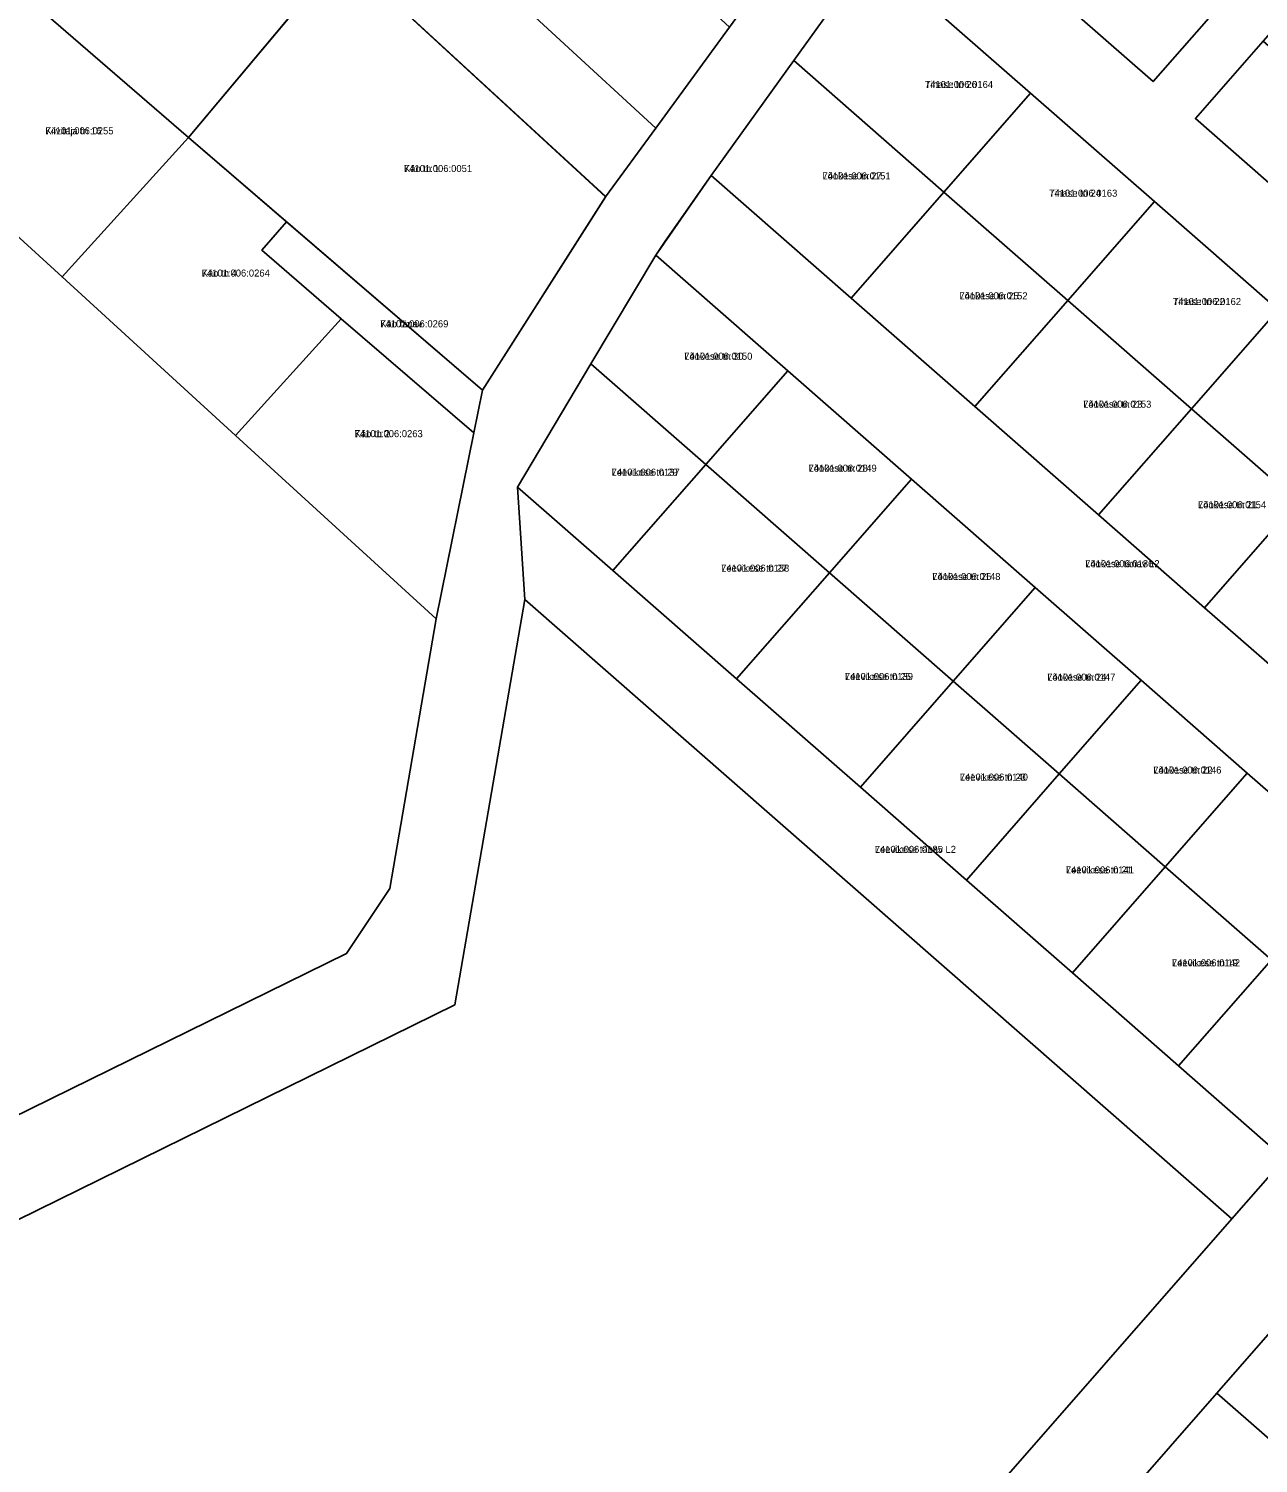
# Model space of a CAD drawing. Extents: x 524000 to 564260, y 6469338 to 6496391.
# Drawn here: x 536750.1 to 537011.8, y 6471813 to 6472118.2 of the extents above; entities that cross this region are included whole.
import ezdxf

# ---------------------------------------------------------------- set-up
doc = ezdxf.new("R2010")
doc.units = 0
for name, color, linetype in [('L_AADRESS', 7, 'Continuous'), ('PIIR', 7, 'Continuous'), ('TUNNUS', 7, 'Continuous')]:
    doc.layers.add(name, color=color, linetype=linetype)

msp = doc.modelspace()

# ---------------------------------------------------------------- linework, layer by layer
at = {"layer": 'PIIR'}
for points in [[(536598.53, 6471787.38), (536691.64, 6471859.49), (536817.72, 6471921.43), (536826.91, 6471935.23), (536836.8, 6471992.63), (536844.78, 6472032.2), (536846.61, 6472041.28), (536872.84, 6472082.4), (536883.51, 6472097.04), (536899.19, 6472118.54), (536915.8, 6472141.31), (536932.4, 6472164.08), (536949.01, 6472186.85), (536965.62, 6472209.62), (536985.97, 6472237.52), (537009.83, 6472283.87), (537016.95, 6472297.73), (537039.93, 6472342.52), (537051.84, 6472365.68), (537062.93, 6472387.24), (537108.26, 6472473.39), (537130.43, 6472505.81), (537193.52, 6472604.34)], [(536952.15, 6471803.3), (537006.16, 6471864.98), (537017.36, 6471877.77), (537037.12, 6471900.35), (537054.57, 6471920.29), (537068.06, 6471935.7), (537087.84, 6471958.29), (537106.28, 6471979.36), (537118.79, 6471993.66), (537138.88, 6472016.61), (537158.97, 6472039.56), (537164.89, 6472046.32), (537178.76, 6472063.41), (537191.4, 6472089.56), (537203.58, 6472114.76), (537222.16, 6472153.23)], [(537027.37, 6472132.15), (537012.83, 6472115.57), (536998.37, 6472099.05), (537028.47, 6472072.68), (537057.09, 6472047.67), (537071.58, 6472064.22), (537086.07, 6472080.77), (537101.2, 6472098.06), (537110.23, 6472090.16), (537106.29, 6472085.66), (537086.2, 6472062.71), (537066.12, 6472039.76), (537092.45, 6472016.71), (537118.79, 6471993.66), (537106.28, 6471979.36), (537083.7, 6471999.12), (537061.13, 6472018.88), (537038.55, 6472038.64), (537015.98, 6472058.4), (536989.64, 6472081.45), (536963.31, 6472104.5), (536936.97, 6472127.55)], [(536963.03, 6472129.99), (536989.36, 6472106.94), (537009.45, 6472129.89)], [(536924.62, 6472127.73), (536912.89, 6472111.41), (536895.29, 6472086.93), (536883.5, 6472070.02), (536869.7, 6472046.88), (536854.08, 6472020.68), (536855.67, 6471996.71), (536840.73, 6471910.48), (536702.98, 6471842.76)], [(537230.56, 6472120.27), (537223.01, 6472104.37), (537210.75, 6472079.08), (537195.93, 6472048.34), (537181.45, 6472031.9), (537176.52, 6472026.23), (537159.73, 6472007.01), (537143.9, 6471988.99), (537135.34, 6471979.21), (537122.84, 6471964.92), (537104.39, 6471943.84), (537084.62, 6471921.26), (537073.06, 6471908.42), (537053.67, 6471885.9), (537033.91, 6471863.34), (537022.7, 6471850.49), (537002.94, 6471827.91), (536983.19, 6471805.36)], [(536722.08, 6472097.38), (536757.16, 6472065.37), (536794.07, 6472031.67), (536836.8, 6471992.63), (536826.91, 6471935.23), (536817.72, 6471921.43), (536691.64, 6471859.49)]]:
    msp.add_lwpolyline(points, dxfattribs=at)
for points in [[(536682.14, 6472247.09), (536696.9, 6472258.31), (536743.83, 6472220.35), (536755.56, 6472210.87), (536793.61, 6472180.1), (536800.84, 6472173.14), (536842.78, 6472134.54), (536883.51, 6472097.04), (536872.84, 6472082.4), (536816.75, 6472134.03), (536788.77, 6472159.81), (536777.64, 6472169.87), (536742.34, 6472198.41), (536730.34, 6472208.11)], [(536753.77, 6472121.18), (536788.77, 6472159.81), (536816.75, 6472134.03), (536784.08, 6472095.07)], [(536842.78, 6472134.54), (536858.46, 6472156.03), (536899.19, 6472118.54), (536883.51, 6472097.04)], [(536963.03, 6472129.99), (536983.11, 6472152.94), (537009.45, 6472129.89), (536989.36, 6472106.94)], [(536816.75, 6472134.09), (536872.86, 6472082.48), (536846.61, 6472041.28), (536784.08, 6472095.07)], [(536722.08, 6472097.38), (536748.09, 6472126.08), (536753.77, 6472121.18), (536784.08, 6472095.07), (536757.16, 6472065.37)], [(536912.89, 6472111.41), (536924.62, 6472127.73), (536931.7, 6472121.53), (536936.97, 6472127.55), (536963.31, 6472104.5), (536944.86, 6472083.43)], [(537028.47, 6472072.68), (536998.37, 6472099.05), (537012.83, 6472115.57), (537042.88, 6472089.21)], [(536895.29, 6472086.93), (536912.89, 6472111.41), (536944.86, 6472083.43), (536925.09, 6472060.84)], [(536944.86, 6472083.43), (536963.31, 6472104.5), (536989.64, 6472081.45), (536971.2, 6472060.38)], [(536757.16, 6472065.37), (536784.08, 6472095.07), (536804.93, 6472077.12), (536799.7, 6472071.05), (536816.59, 6472056.49), (536794.07, 6472031.67)], [(536883.5, 6472070.02), (536885.55, 6472072.96), (536895.29, 6472086.93), (536925.09, 6472060.84), (536951.43, 6472037.79), (536977.76, 6472014.73), (537000.34, 6471994.98), (537022.91, 6471975.22), (537045.49, 6471955.46), (537068.06, 6471935.7), (537054.57, 6471920.29), (537032, 6471940.05), (537009.42, 6471959.8), (536986.85, 6471979.56), (536964.27, 6471999.32), (536937.94, 6472022.37), (536911.6, 6472045.42)], [(536925.09, 6472060.84), (536944.86, 6472083.43), (536971.2, 6472060.38), (536951.43, 6472037.79)], [(536971.2, 6472060.38), (536989.64, 6472081.45), (537015.98, 6472058.4), (536997.54, 6472037.33)], [(536799.7, 6472071.05), (536804.93, 6472077.12), (536846.61, 6472041.28), (536844.78, 6472032.2), (536816.59, 6472056.49)], [(536869.7, 6472046.88), (536883.5, 6472070.02), (536911.6, 6472045.42), (536894.15, 6472025.48)], [(536951.43, 6472037.79), (536971.2, 6472060.38), (536997.54, 6472037.33), (536977.76, 6472014.73)], [(536997.54, 6472037.33), (537015.98, 6472058.4), (537038.55, 6472038.64), (537020.11, 6472017.57)], [(536794.07, 6472031.67), (536816.59, 6472056.49), (536844.78, 6472032.2), (536836.8, 6471992.63)], [(536854.08, 6472020.68), (536869.7, 6472046.88), (536894.15, 6472025.48), (536874.39, 6472002.91)], [(536894.15, 6472025.48), (536911.6, 6472045.42), (536937.94, 6472022.37), (536920.48, 6472002.43)], [(536977.76, 6472014.73), (536997.54, 6472037.33), (537020.11, 6472017.57), (537000.34, 6471994.98)], [(536874.39, 6472002.91), (536894.15, 6472025.48), (536920.48, 6472002.43), (536900.72, 6471979.86)], [(536920.48, 6472002.43), (536937.94, 6472022.37), (536964.27, 6471999.32), (536946.82, 6471979.38)], [(536854.08, 6472020.68), (536874.39, 6472002.91), (536900.72, 6471979.86), (536927.06, 6471956.81), (536949.64, 6471937.05), (536972.21, 6471917.29), (536994.78, 6471897.53), (537017.36, 6471877.77), (537006.16, 6471864.98), (536855.67, 6471996.71)], [(537000.34, 6471994.98), (537020.11, 6472017.57), (537042.69, 6471997.81), (537022.91, 6471975.22)], [(536900.72, 6471979.86), (536920.48, 6472002.43), (536946.82, 6471979.38), (536927.06, 6471956.81)], [(536702.98, 6471842.76), (536840.73, 6471910.48), (536855.67, 6471996.71), (537006.16, 6471864.98), (536952.15, 6471803.3), (536913.09, 6471628.19), (536798.02, 6471487.54), (536531.97, 6471723.71), (536543.17, 6471731.63), (536570.23, 6471750.75), (536574.14, 6471753.52), (536582.32, 6471757.47), (536609.19, 6471770.43), (536610.81, 6471771.56), (536627.08, 6471782.97), (536670.78, 6471813.61), (536682.94, 6471824.61)], [(536946.82, 6471979.38), (536964.27, 6471999.32), (536986.85, 6471979.56), (536969.39, 6471959.62)], [(536927.06, 6471956.81), (536946.82, 6471979.38), (536969.39, 6471959.62), (536949.64, 6471937.05)], [(536969.39, 6471959.62), (536986.85, 6471979.56), (537009.42, 6471959.8), (536991.97, 6471939.86)], [(536949.64, 6471937.05), (536969.39, 6471959.62), (536991.97, 6471939.86), (536972.21, 6471917.29)], [(536991.97, 6471939.86), (537009.42, 6471959.8), (537032, 6471940.05), (537014.54, 6471920.11)], [(536972.21, 6471917.29), (536991.97, 6471939.86), (537014.54, 6471920.11), (536994.78, 6471897.53)], [(536994.78, 6471897.53), (537014.54, 6471920.11), (537037.12, 6471900.35), (537017.36, 6471877.77)], [(537022.7, 6471850.49), (537045.26, 6471830.74), (537025.51, 6471808.17), (537002.94, 6471827.91)], [(537002.94, 6471827.91), (537025.51, 6471808.17), (537005.76, 6471785.59), (536983.19, 6471805.36)]]:
    msp.add_lwpolyline(points, close=True, dxfattribs=at)

# ---------------------------------------------------------------- texts
at = {"layer": 'L_AADRESS'}
for s, p in [('Tihase tn 26', (536940.81, 6472105.58)), ('Kiivitaja tn 16', (536753.61, 6472095.73)), ('Käo tn 1', (536829.93, 6472087.69)), ('Lõokese tn 27', (536919, 6472086.12)), ('Tihase tn 24', (536967.25, 6472082.44)), ('Käo tn 4', (536786.88, 6472065.45)), ('Lõokese tn 25', (536948.15, 6472060.61)), ('Tihase tn 22', (536993.59, 6472059.39)), ('Käo tänav', (536824.88, 6472054.66)), ('Lõokese tn 30', (536889.58, 6472047.75)), ('Lõokese tn 23', (536974.49, 6472037.55)), ('Käo tn 2', (536819.43, 6472031.28)), ('Leevikese tn 29', (536874.11, 6472023.08)), ('Lõokese tn 28', (536916.04, 6472023.93)), ('Lõokese tn 21', (536998.93, 6472016.16)), ('Leevikese tn 27', (536897.43, 6472002.67)), ('Lõokese tänav L2', (536974.92, 6472003.61)), ('Lõokese tn 26', (536942.38, 6472000.88)), ('Leevikese tn 25', (536923.77, 6471979.62)), ('Lõokese tn 24', (536966.83, 6471979.47)), ('Lõokese tn 22', (536989.41, 6471959.71)), ('Leevikese tn 23', (536948.23, 6471958.21)), ('Leevikese tänav L2', (536930.13, 6471942.83)), ('Leevikese tn 21', (536970.8, 6471938.46)), ('Leevikese tn 19', (536993.38, 6471918.7))]:
    msp.add_text(s, height=1.5, dxfattribs=at).set_placement(p)
at = {"layer": 'TUNNUS'}
for s, p in [('74101:006:0164', (536940.81, 6472105.58)), ('74101:006:0255', (536753.61, 6472095.73)), ('74101:006:0051', (536829.93, 6472087.69)), ('74101:006:0151', (536919, 6472086.12)), ('74101:006:0163', (536967.25, 6472082.44)), ('74101:006:0264', (536786.88, 6472065.45)), ('74101:006:0152', (536948.15, 6472060.61)), ('74101:006:0162', (536993.59, 6472059.39)), ('74101:006:0269', (536824.88, 6472054.66)), ('74101:006:0150', (536889.58, 6472047.75)), ('74101:006:0153', (536974.49, 6472037.55)), ('74101:006:0263', (536819.43, 6472031.28)), ('74101:006:0137', (536874.11, 6472023.08)), ('74101:006:0149', (536916.04, 6472023.93)), ('74101:006:0154', (536998.93, 6472016.16)), ('74101:006:0138', (536897.43, 6472002.67)), ('74101:006:0186', (536974.92, 6472003.61)), ('74101:006:0148', (536942.38, 6472000.88)), ('74101:006:0139', (536923.77, 6471979.62)), ('74101:006:0147', (536966.83, 6471979.47)), ('74101:006:0146', (536989.41, 6471959.71)), ('74101:006:0140', (536948.23, 6471958.21)), ('74101:006:0185', (536930.13, 6471942.83)), ('74101:006:0141', (536970.8, 6471938.46)), ('74101:006:0142', (536993.38, 6471918.7))]:
    msp.add_text(s, height=1.5, dxfattribs=at).set_placement(p)

doc.saveas('drawing.dxf')
